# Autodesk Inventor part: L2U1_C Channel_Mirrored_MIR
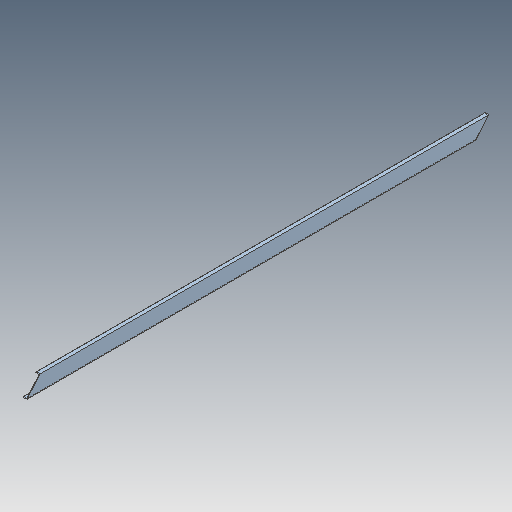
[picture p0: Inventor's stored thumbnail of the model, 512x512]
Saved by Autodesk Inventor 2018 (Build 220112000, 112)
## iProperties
Created: 2018-02
Part Number: L2U1_C Channel_Mirrored_MIR
Material: Steel, Mild
Document SubType Name: Modeling
Designer: STK
Density: 7.85 g/cm^3
Appearance: Semi-Polished
Author: STK
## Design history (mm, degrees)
derived "L2U1_C Channel_Mirrored.ipt"
feature "Solid1::L2U1_C Channel_Mirrored.ipt" dims "d0" = 10
tag "TaggingFeature1"
body "Solid1"
